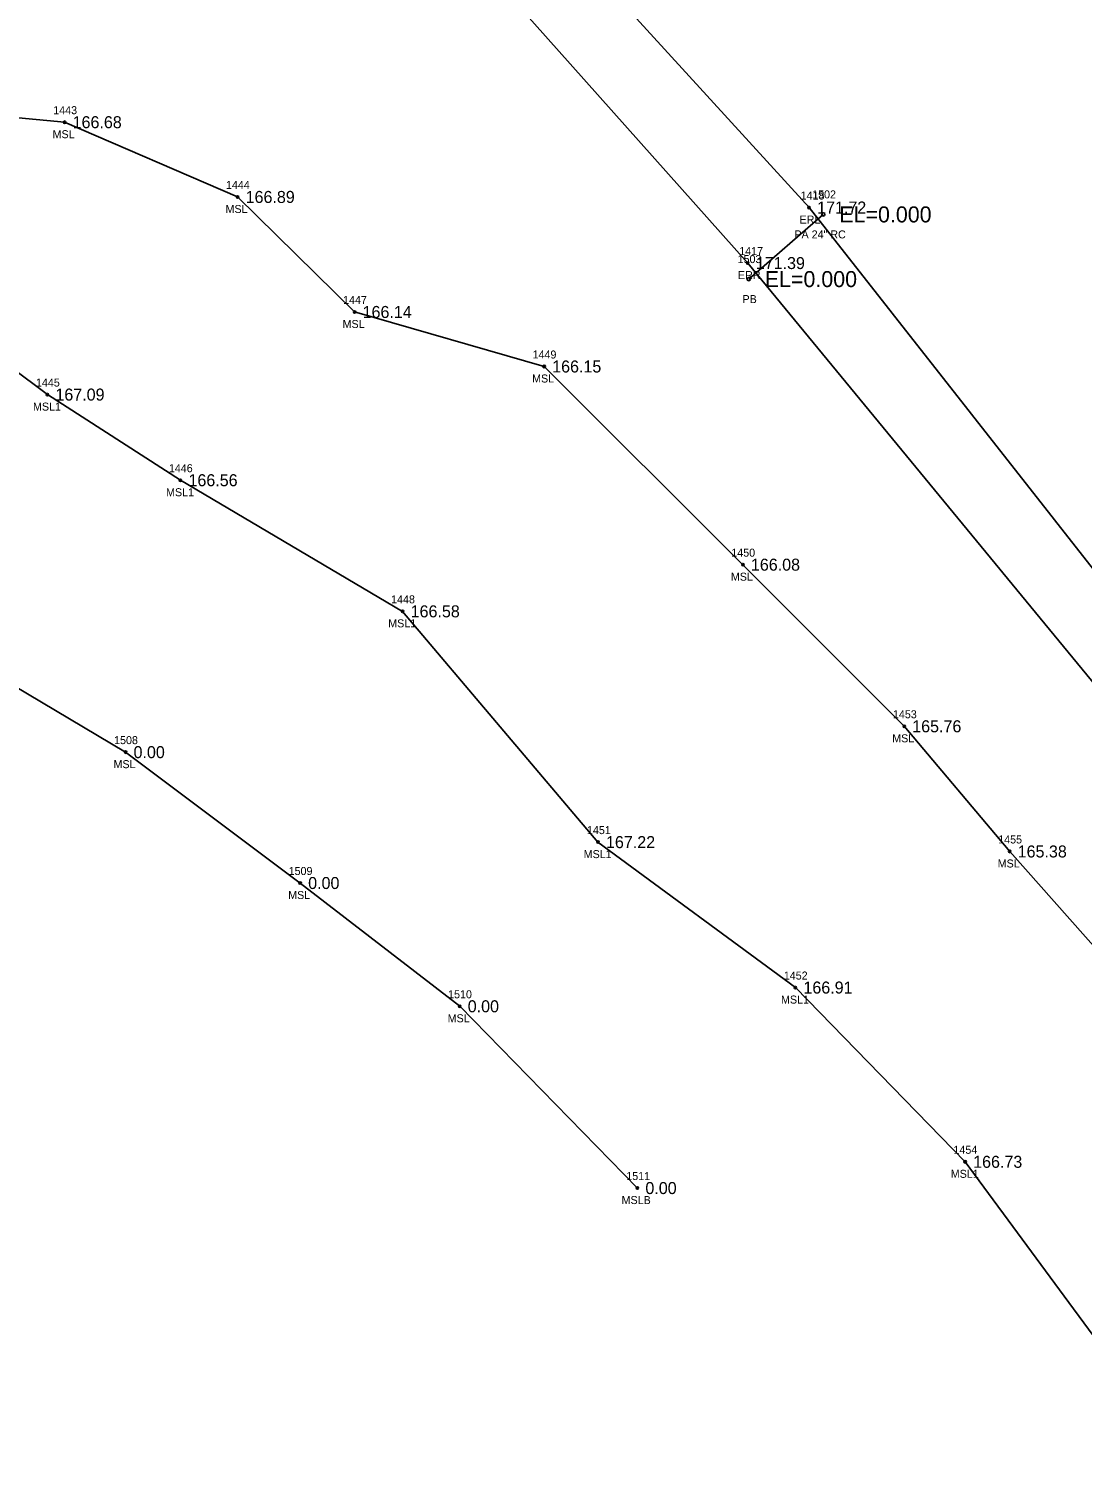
# Model space of a CAD drawing. Extents: x 1969685 to 1970577, y 796315 to 797503.
# Drawn here: x 1969997.2 to 1970128.7, y 796924.5 to 797104.8 of the extents above; entities that cross this region are included whole.
import ezdxf

# ---------------------------------------------------------------- set-up
doc = ezdxf.new("R2010")
doc.units = 0
for name, color, linetype in [('RD_EX_DR_Pipe', 7, 'Continuous'), ('RD_EX_DR_Pipe_txCode', 7, 'Continuous'), ('RD_EX_Misc', 7, 'Continuous'), ('RD_EX_Misc_txCode', 7, 'Continuous'), ('RD_EX_Road', 7, 'Continuous'), ('RD_EX_Road_txCode', 7, 'Continuous'), ('RD_EX_TX_Misc_ELEV', 7, 'Continuous'), ('RD_EX_TX_Road_ELEV', 7, 'Continuous'), ('RD_SMD_Locator', 7, 'Continuous'), ('RD_TX_Pipe_ElevEX', 7, 'Continuous')]:
    doc.layers.add(name, color=color, linetype=linetype)

msp = doc.modelspace()

# ---------------------------------------------------------------- linework, layer by layer
at = {"layer": 'RD_EX_DR_Pipe'}
msp.add_line((1970096.4, 797081.66), (1970087.09, 797073.58), dxfattribs=at)
at = {"layer": 'RD_EX_Misc'}
for points in [[(1969901.95, 797123.78), (1969973.72, 797095.81), (1970001.64, 797093.18), (1970023.25, 797083.84), (1970037.86, 797069.47), (1970061.54, 797062.66), (1970086.36, 797037.9), (1970106.51, 797017.71), (1970119.68, 797002.07), (1970134.67, 796985.14)], [(1969878.63, 797103.96), (1969914.63, 797059.74), (1969934.33, 797079.31), (1969985.27, 797069.8), (1969999.49, 797059.15), (1970016.11, 797048.45), (1970043.86, 797032.07), (1970068.26, 797003.24), (1970092.92, 796985.07), (1970114.12, 796963.3), (1970132.42, 796938.45)], [(1969952.07, 797062.33), (1969952.57, 797055.41), (1969967.4, 797042.05), (1969991.72, 797024.88), (1970009.25, 797014.48), (1970031.06, 796998.13), (1970050.99, 796982.73), (1970073.18, 796960.02)]]:
    msp.add_lwpolyline(points, dxfattribs=at)
at = {"layer": 'RD_EX_Road'}
for points in [[(1969700.74, 797501.33), (1969779.98, 797423.39), (1969814.72, 797391.2), (1969880.84, 797321.11), (1969950.92, 797234.98), (1970023.24, 797160.71), (1970094.63, 797082.52), (1970155.94, 797004.5), (1970226.04, 796929.95), (1970305.25, 796840.26), (1970331.41, 796808.37), (1970366.95, 796762.12), (1970420.55, 796674.34), (1970475.41, 796571.94), (1970519.62, 796482.24), (1970570.43, 796387.6)], [(1969686.81, 797489.23), (1969769.62, 797412.05), (1969806.95, 797381.52), (1969873.82, 797315.12), (1969942.63, 797227.86), (1970016.3, 797154.94), (1970086.97, 797075.58), (1970150.3, 796998.65), (1970220.21, 796923.5), (1970297.55, 796833.97), (1970324.51, 796802.07), (1970359.87, 796756.6), (1970413.8, 796671.17), (1970467.81, 796568.38), (1970512.42, 796477.88), (1970563.2, 796383.6)]]:
    msp.add_lwpolyline(points, dxfattribs=at)
at = {"layer": 'RD_SMD_Locator'}
for centre, radius in [((1970001.64, 797093.18), 0.15), ((1970023.25, 797083.84), 0.15), ((1970094.63, 797082.52), 0.15), ((1970096.4, 797081.66), 0.2), ((1970086.97, 797075.58), 0.15), ((1970087.09, 797073.58), 0.2), ((1970037.86, 797069.47), 0.15), ((1970061.54, 797062.66), 0.15), ((1969999.49, 797059.15), 0.15), ((1970016.11, 797048.45), 0.15), ((1970086.36, 797037.9), 0.15), ((1970043.86, 797032.07), 0.15), ((1970106.51, 797017.71), 0.15), ((1970009.25, 797014.48), 0.15), ((1970068.26, 797003.24), 0.15), ((1970119.68, 797002.07), 0.15), ((1970031.06, 796998.13), 0.15), ((1970092.92, 796985.07), 0.15), ((1970050.99, 796982.73), 0.15), ((1970114.12, 796963.3), 0.15), ((1970073.18, 796960.02), 0.15)]:
    msp.add_circle(centre, radius, dxfattribs=at)

# ---------------------------------------------------------------- texts
at = {"layer": 'RD_EX_DR_Pipe_txCode'}
for s, p in [('1502', (1970095.01, 797083.66)), ('PA 24" RC', (1970092.79, 797078.66)), ('1503', (1970085.7, 797075.58)), ('PB', (1970086.31, 797070.58))]:
    msp.add_text(s, height=1, dxfattribs=at).set_placement(p)
at = {"layer": 'RD_EX_Misc_txCode'}
for s, p in [('1443', (1970000.22, 797094.18)), ('MSL', (1970000.14, 797091.18)), ('1444', (1970021.79, 797084.84)), ('MSL', (1970021.74, 797081.84)), ('1447', (1970036.42, 797070.47)), ('MSL', (1970036.36, 797067.47)), ('1449', (1970060.09, 797063.66)), ('1445', (1969998.06, 797060.15)), ('MSL', (1970060.03, 797060.66)), ('MSL1', (1969997.69, 797057.15)), ('1446', (1970014.66, 797049.45)), ('MSL1', (1970014.31, 797046.45)), ('1450', (1970084.91, 797038.9)), ('MSL', (1970084.86, 797035.9)), ('1448', (1970042.42, 797033.07)), ('MSL1', (1970042.06, 797030.07)), ('1453', (1970105.1, 797018.71)), ('1508', (1970007.82, 797015.48)), ('MSL', (1970105.01, 797015.71)), ('MSL', (1970007.75, 797012.48)), ('1451', (1970066.88, 797004.24)), ('1455', (1970118.25, 797003.07)), ('MSL1', (1970066.47, 797001.24)), ('MSL', (1970118.18, 797000.07)), ('1509', (1970029.62, 796999.13)), ('MSL', (1970029.56, 796996.13)), ('1452', (1970091.47, 796986.07)), ('1510', (1970049.54, 796983.73)), ('MSL1', (1970091.12, 796983.07)), ('MSL', (1970049.48, 796980.73)), ('1454', (1970112.66, 796964.3)), ('1511', (1970071.79, 796961.02)), ('MSL1', (1970112.32, 796961.3)), ('MSLB', (1970071.21, 796958.02))]:
    msp.add_text(s, height=1, dxfattribs=at).set_placement(p)
at = {"layer": 'RD_EX_Road_txCode'}
for s, p in [('1418', (1970093.57, 797083.52)), ('ERL', (1970093.43, 797080.52)), ('1417', (1970085.9, 797076.58)), ('ERR', (1970085.74, 797073.58))]:
    msp.add_text(s, height=1, dxfattribs=at).set_placement(p)
at = {"layer": 'RD_EX_TX_Misc_ELEV'}
for s, p in [('166.68', (1970002.64, 797092.43)), ('166.89', (1970024.25, 797083.09)), ('166.14', (1970038.86, 797068.72)), ('166.15', (1970062.54, 797061.91)), ('167.09', (1970000.49, 797058.4)), ('166.56', (1970017.11, 797047.7)), ('166.08', (1970087.36, 797037.15)), ('166.58', (1970044.86, 797031.32)), ('165.76', (1970107.51, 797016.96)), ('0.00', (1970010.25, 797013.73)), ('167.22', (1970069.26, 797002.49)), ('165.38', (1970120.68, 797001.32)), ('0.00', (1970032.06, 796997.38)), ('166.91', (1970093.92, 796984.32)), ('0.00', (1970051.99, 796981.98)), ('166.73', (1970115.12, 796962.55)), ('0.00', (1970074.18, 796959.27))]:
    msp.add_text(s, height=1.5, dxfattribs=at).set_placement(p)
at = {"layer": 'RD_EX_TX_Road_ELEV'}
for s, p in [('171.72', (1970095.63, 797081.77)), ('171.39', (1970087.97, 797074.83))]:
    msp.add_text(s, height=1.5, dxfattribs=at).set_placement(p)
at = {"layer": 'RD_TX_Pipe_ElevEX'}
for p in [(1970098.4, 797080.66), (1970089.09, 797072.58)]:
    msp.add_text('EL=0.000', height=2, dxfattribs=at).set_placement(p)

doc.saveas('drawing.dxf')
